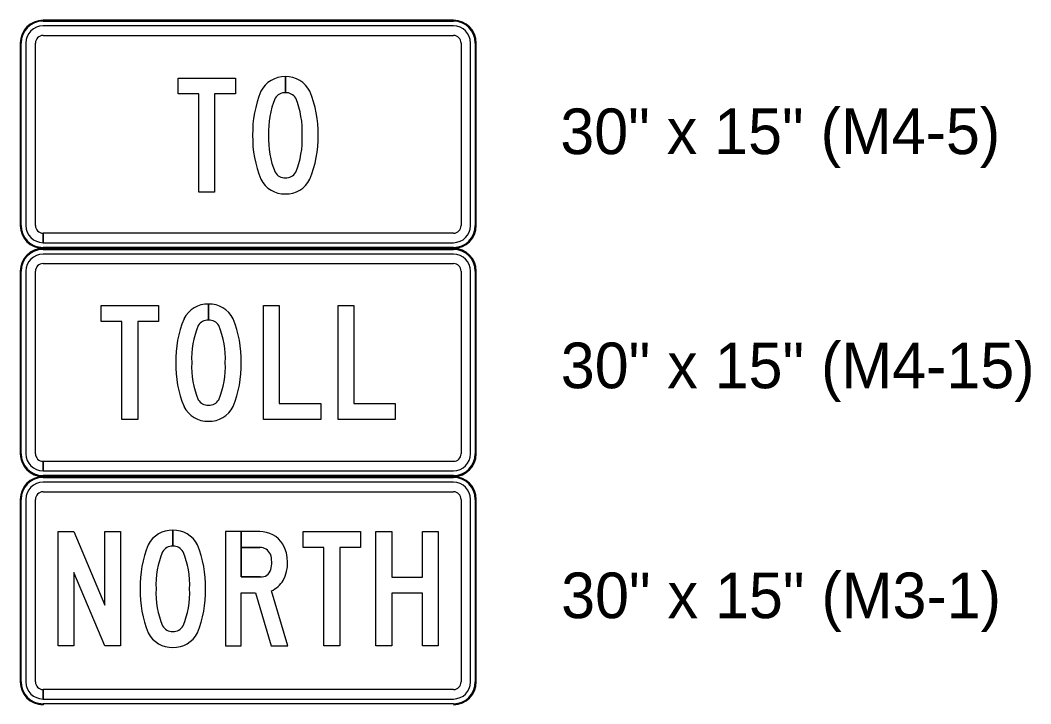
# Model space of a CAD drawing. Extents: x 17890587 to 17890754, y 17897693 to 17897992.
# Drawn here: x 17890612.323 to 17890616.81, y 17897879.973 to 17897883.006 of the extents above; entities that cross this region are included whole.
import ezdxf

# ---------------------------------------------------------------- set-up
doc = ezdxf.new("R2010")
doc.units = 0
for name, color, linetype in [('GSBWFill', 7, 'Continuous'), ('GSColorFill', 7, 'Continuous'), ('GSOutline', 7, 'Continuous'), ('TextMisc', 7, 'Continuous')]:
    doc.layers.add(name, color=color, linetype=linetype)

msp = doc.modelspace()

# ---------------------------------------------------------------- linework, layer by layer
at = {"layer": 'GSBWFill'}
for p, q in [((17890613.5003, 17897882.6844), (17890613.5003, 17897882.7557)), ((17890613.5003, 17897882.7557), (17890613.5003, 17897882.6844))]:
    msp.add_line(p, q, dxfattribs=at)
msp.add_lwpolyline([(17890613.1161, 17897882.6787), (17890613.0239, 17897882.6787), (17890613.0239, 17897882.7496), (17890613.2782, 17897882.7496), (17890613.2782, 17897882.6787), (17890613.1859, 17897882.6787), (17890613.1859, 17897882.2434), (17890613.1161, 17897882.2434)], close=True, dxfattribs=at)
for centre, major_axis, start_param, end_param in [((17890613.4962, 17897882.6365), (0, 0.1193), 6.248265, 7.383959), ((17890613.5044, 17897882.6365), (0, 0.1193), 5.182411, 6.317893), ((17890613.8275, 17897882.5051), (0, 0.48), 1.174158, 1.59042), ((17890613.173, 17897882.5051), (0, 0.48), 4.692766, 5.109028), ((17890613.7966, 17897882.5127), (0, 0.377), 1.169623, 1.616135), ((17890613.4976, 17897882.6335), (0, 0.051), 6.22959, 7.30809), ((17890613.503, 17897882.6335), (0, 0.051), 5.258281, 6.336283), ((17890613.204, 17897882.5127), (0, 0.377), 4.667051, 5.113562), ((17890613.8275, 17897882.4862), (0, 0.48), 1.551173, 1.967435), ((17890613.7966, 17897882.4786), (0, 0.377), 1.525458, 1.97197), ((17890613.204, 17897882.4786), (0, 0.377), 4.311216, 4.757727), ((17890613.173, 17897882.4862), (0, 0.48), 4.31575, 4.732012), ((17890613.4976, 17897882.3578), (0, 0.051), 2.116688, 3.195188), ((17890613.503, 17897882.3578), (0, 0.051), 3.087997, 4.166497), ((17890613.4962, 17897882.3548), (0, 0.1193), 2.040819, 3.176513), ((17890613.5044, 17897882.3548), (0, 0.1193), 3.106673, 4.242367)]:
    msp.add_ellipse(centre, major_axis=major_axis, ratio=0.985, start_param=start_param, end_param=end_param, dxfattribs=at)
at = {"layer": 'GSColorFill'}
for p, q in [((17890614.2465, 17897883.006), (17890612.4241, 17897883.006)), ((17890614.2465, 17897883.006), (17890612.4241, 17897883.006)), ((17890612.4241, 17897883.0018), (17890614.2465, 17897883.0018)), ((17890614.2465, 17897882.9807), (17890612.4241, 17897882.9807)), ((17890612.4241, 17897882.9385), (17890614.2465, 17897882.9385)), ((17890612.3229, 17897882.9048), (17890612.3229, 17897882.0949)), ((17890612.3229, 17897882.9048), (17890612.3229, 17897882.0949)), ((17890612.3271, 17897882.0949), (17890612.3271, 17897882.9048)), ((17890612.3482, 17897882.9048), (17890612.3482, 17897882.0949)), ((17890612.3904, 17897882.0949), (17890612.3904, 17897882.9048)), ((17890614.2802, 17897882.9048), (17890614.2802, 17897882.0949)), ((17890614.3224, 17897882.0949), (17890614.3224, 17897882.9048)), ((17890614.3435, 17897882.9048), (17890614.3435, 17897882.0949)), ((17890614.3477, 17897882.0949), (17890614.3477, 17897882.9048)), ((17890614.3477, 17897882.0949), (17890614.3477, 17897882.9048)), ((17890613.5003, 17897882.6844), (17890613.5003, 17897882.7557)), ((17890613.5003, 17897882.7557), (17890613.5003, 17897882.6844)), ((17890612.4241, 17897882.0189), (17890612.4241, 17897882.0611)), ((17890614.2465, 17897882.0611), (17890612.4246, 17897882.0611)), ((17890612.4246, 17897882.0611), (17890612.4246, 17897882.0189)), ((17890612.4246, 17897882.0189), (17890614.2465, 17897882.0189)), ((17890612.4241, 17897881.9936), (17890612.4241, 17897881.9979)), ((17890612.4241, 17897881.9936), (17890614.2465, 17897881.9936)), ((17890614.2465, 17897881.9979), (17890612.4242, 17897881.9979)), ((17890612.4242, 17897881.9979), (17890612.4242, 17897881.9936)), ((17890612.4242, 17897881.9936), (17890614.2465, 17897881.9936)), ((17890614.2465, 17897881.9936), (17890612.4242, 17897881.9936)), ((17890614.2465, 17897881.9936), (17890612.4242, 17897881.9936)), ((17890612.4242, 17897881.9894), (17890614.2465, 17897881.9894)), ((17890614.2465, 17897881.9683), (17890612.4242, 17897881.9683)), ((17890612.3229, 17897881.8924), (17890612.3229, 17897881.0825)), ((17890612.3229, 17897881.8924), (17890612.3229, 17897881.0825)), ((17890612.3271, 17897881.0825), (17890612.3271, 17897881.8924)), ((17890612.3482, 17897881.8924), (17890612.3482, 17897881.0825)), ((17890612.3904, 17897881.0825), (17890612.3904, 17897881.8924)), ((17890612.4242, 17897881.9261), (17890614.2465, 17897881.9261)), ((17890614.2802, 17897881.8924), (17890614.2802, 17897881.0825)), ((17890614.3224, 17897881.0825), (17890614.3224, 17897881.8924)), ((17890614.3435, 17897881.8924), (17890614.3435, 17897881.0825)), ((17890614.3477, 17897881.0825), (17890614.3477, 17897881.8924)), ((17890614.3477, 17897881.0825), (17890614.3477, 17897881.8924)), ((17890613.1589, 17897881.6754), (17890613.1589, 17897881.7467)), ((17890613.1589, 17897881.7467), (17890613.1589, 17897881.6754)), ((17890612.4242, 17897881.0065), (17890612.4242, 17897881.0487)), ((17890614.2465, 17897881.0487), (17890612.4246, 17897881.0487)), ((17890612.4246, 17897881.0487), (17890612.4246, 17897881.0065)), ((17890612.4242, 17897880.9812), (17890612.4242, 17897880.9855)), ((17890614.2465, 17897880.9855), (17890612.4242, 17897880.9855)), ((17890612.4242, 17897880.9855), (17890612.4242, 17897880.9812)), ((17890612.4246, 17897881.0065), (17890614.2465, 17897881.0065)), ((17890614.2465, 17897880.9812), (17890612.4242, 17897880.9812)), ((17890614.2465, 17897880.9812), (17890612.4242, 17897880.9812)), ((17890612.4242, 17897880.9812), (17890614.2465, 17897880.9812)), ((17890612.4242, 17897880.9812), (17890614.2465, 17897880.9812)), ((17890612.4242, 17897880.977), (17890614.2465, 17897880.977)), ((17890614.2465, 17897880.9559), (17890612.4242, 17897880.9559)), ((17890612.4242, 17897880.9137), (17890614.2465, 17897880.9137)), ((17890612.3229, 17897880.88), (17890612.3229, 17897880.0701)), ((17890612.3229, 17897880.88), (17890612.3229, 17897880.0701)), ((17890612.3272, 17897880.0701), (17890612.3272, 17897880.88)), ((17890612.3483, 17897880.88), (17890612.3483, 17897880.0701)), ((17890612.3904, 17897880.0701), (17890612.3904, 17897880.88)), ((17890614.2803, 17897880.88), (17890614.2803, 17897880.0701)), ((17890614.3224, 17897880.0701), (17890614.3224, 17897880.88)), ((17890614.3435, 17897880.88), (17890614.3435, 17897880.0701)), ((17890614.3477, 17897880.0701), (17890614.3477, 17897880.88)), ((17890614.3477, 17897880.0701), (17890614.3477, 17897880.88)), ((17890613.0005, 17897880.6718), (17890613.0005, 17897880.7431)), ((17890613.0005, 17897880.7431), (17890613.0005, 17897880.6718)), ((17890613.0005, 17897880.6718), (17890613.0005, 17897880.7431)), ((17890613.0005, 17897880.7431), (17890613.0005, 17897880.6718)), ((17890613.5106, 17897880.2307), (17890613.4384, 17897880.4736)), ((17890612.4242, 17897879.9941), (17890612.4242, 17897880.0363)), ((17890614.2465, 17897880.0363), (17890612.4246, 17897880.0363)), ((17890612.4246, 17897880.0363), (17890612.4246, 17897879.9941)), ((17890612.4242, 17897879.9688), (17890612.4242, 17897879.9731)), ((17890614.2465, 17897879.9731), (17890612.4242, 17897879.9731)), ((17890612.4242, 17897879.9731), (17890612.4242, 17897879.9688)), ((17890612.4246, 17897879.9941), (17890614.2465, 17897879.9941))]:
    msp.add_line(p, q, dxfattribs=at)
for points in [[(17890613.1161, 17897882.6787), (17890613.0239, 17897882.6787), (17890613.0239, 17897882.7496), (17890613.2782, 17897882.7496), (17890613.2782, 17897882.6787), (17890613.1859, 17897882.6787), (17890613.1859, 17897882.2434), (17890613.1161, 17897882.2434)], [(17890612.7747, 17897881.6697), (17890612.6825, 17897881.6697), (17890612.6825, 17897881.7405), (17890612.9368, 17897881.7405), (17890612.9368, 17897881.6697), (17890612.8445, 17897881.6697), (17890612.8445, 17897881.2343), (17890612.7747, 17897881.2343)], [(17890613.4027, 17897881.7405), (17890613.4725, 17897881.7405), (17890613.4725, 17897881.3052), (17890613.6569, 17897881.3052), (17890613.6569, 17897881.2343), (17890613.4027, 17897881.2343)], [(17890613.7339, 17897881.7405), (17890613.8037, 17897881.7405), (17890613.8037, 17897881.3052), (17890613.9881, 17897881.3052), (17890613.9881, 17897881.2343), (17890613.7339, 17897881.2343)], [(17890612.5612, 17897880.7369), (17890612.6986, 17897880.4109), (17890612.6986, 17897880.7369), (17890612.7684, 17897880.7369), (17890612.7684, 17897880.2307), (17890612.6986, 17897880.2307), (17890612.5615, 17897880.556), (17890612.5615, 17897880.2307), (17890612.4917, 17897880.2307), (17890612.4917, 17897880.7369)], [(17890612.5612, 17897880.7369), (17890612.6986, 17897880.4109), (17890612.6986, 17897880.7369), (17890612.7684, 17897880.7369), (17890612.7684, 17897880.2307), (17890612.6986, 17897880.2307), (17890612.5615, 17897880.556), (17890612.5615, 17897880.2307), (17890612.4917, 17897880.2307), (17890612.4917, 17897880.7369)], [(17890612.5612, 17897880.7369), (17890612.6986, 17897880.4109), (17890612.6986, 17897880.7369), (17890612.7684, 17897880.7369), (17890612.7684, 17897880.2307), (17890612.6986, 17897880.2307), (17890612.5615, 17897880.556), (17890612.5615, 17897880.2307), (17890612.4917, 17897880.2307), (17890612.4917, 17897880.7369)], [(17890613.6715, 17897880.666), (17890613.5793, 17897880.666), (17890613.5793, 17897880.7369), (17890613.8336, 17897880.7369), (17890613.8336, 17897880.666), (17890613.7413, 17897880.666), (17890613.7413, 17897880.2307), (17890613.6715, 17897880.2307)], [(17890613.6715, 17897880.666), (17890613.5793, 17897880.666), (17890613.5793, 17897880.7369), (17890613.8336, 17897880.7369), (17890613.8336, 17897880.666), (17890613.7413, 17897880.666), (17890613.7413, 17897880.2307), (17890613.6715, 17897880.2307)], [(17890613.6715, 17897880.666), (17890613.5793, 17897880.666), (17890613.5793, 17897880.7369), (17890613.8336, 17897880.7369), (17890613.8336, 17897880.666), (17890613.7413, 17897880.666), (17890613.7413, 17897880.2307), (17890613.6715, 17897880.2307)], [(17890613.9023, 17897880.7369), (17890613.9721, 17897880.7369), (17890613.9721, 17897880.5344), (17890614.1092, 17897880.5344), (17890614.1092, 17897880.7369), (17890614.179, 17897880.7369), (17890614.179, 17897880.2307), (17890614.1092, 17897880.2307), (17890614.1092, 17897880.4636), (17890613.9721, 17897880.4636), (17890613.9721, 17897880.2307), (17890613.9023, 17897880.2307)], [(17890613.9023, 17897880.7369), (17890613.9721, 17897880.7369), (17890613.9721, 17897880.5344), (17890614.1092, 17897880.5344), (17890614.1092, 17897880.7369), (17890614.179, 17897880.7369), (17890614.179, 17897880.2307), (17890614.1092, 17897880.2307), (17890614.1092, 17897880.4636), (17890613.9721, 17897880.4636), (17890613.9721, 17897880.2307), (17890613.9023, 17897880.2307)], [(17890613.9023, 17897880.7369), (17890613.9721, 17897880.7369), (17890613.9721, 17897880.5344), (17890614.1092, 17897880.5344), (17890614.1092, 17897880.7369), (17890614.179, 17897880.7369), (17890614.179, 17897880.2307), (17890614.1092, 17897880.2307), (17890614.1092, 17897880.4636), (17890613.9721, 17897880.4636), (17890613.9721, 17897880.2307), (17890613.9023, 17897880.2307)]]:
    msp.add_lwpolyline(points, close=True, dxfattribs=at)
for points in [[(17890613.3863, 17897880.7369), (17890613.2339, 17897880.7369), (17890613.2339, 17897880.2307), (17890613.3037, 17897880.2307), (17890613.3037, 17897880.4651), (17890613.3681, 17897880.4651), (17890613.4377, 17897880.2307), (17890613.5106, 17897880.2307)], [(17890613.3889, 17897880.536), (17890613.3037, 17897880.536), (17890613.3037, 17897880.7369), (17890613.2339, 17897880.7369), (17890613.2339, 17897880.2307)], [(17890613.3889, 17897880.536), (17890613.3037, 17897880.536), (17890613.3037, 17897880.7369), (17890613.2339, 17897880.7369), (17890613.2339, 17897880.2307)], [(17890613.3863, 17897880.7369), (17890613.3037, 17897880.7369), (17890613.3037, 17897880.666), (17890613.3863, 17897880.666)], [(17890613.3863, 17897880.7369), (17890613.3037, 17897880.7369), (17890613.3037, 17897880.666), (17890613.3863, 17897880.666)], [(17890613.3863, 17897880.666), (17890613.3037, 17897880.666), (17890613.3037, 17897880.536), (17890613.3889, 17897880.536)], [(17890613.2339, 17897880.2307), (17890613.3037, 17897880.2307), (17890613.3037, 17897880.4651), (17890613.3681, 17897880.4651), (17890613.4377, 17897880.2307), (17890613.5106, 17897880.2307), (17890613.4384, 17897880.4736)], [(17890613.2339, 17897880.2307), (17890613.3037, 17897880.2307), (17890613.3037, 17897880.4651), (17890613.3681, 17897880.4651), (17890613.4377, 17897880.2307), (17890613.5106, 17897880.2307), (17890613.4384, 17897880.4736)]]:
    msp.add_lwpolyline(points, dxfattribs=at)
for centre, radius, start, end in [((17890612.4241, 17897882.9048), 0.1012, 90, 180), ((17890612.4241, 17897882.9048), 0.1012, 90, 180), ((17890614.2465, 17897882.9048), 0.1012, 0, 90), ((17890614.2465, 17897882.9048), 0.1012, 0, 90), ((17890612.4241, 17897882.9048), 0.097, 90, 180), ((17890612.4241, 17897882.9048), 0.0759, 90, 180), ((17890614.2465, 17897882.9048), 0.097, 0, 90), ((17890614.2465, 17897882.9048), 0.0759, 0, 90), ((17890612.4241, 17897882.9048), 0.0337, 90, 180), ((17890614.2465, 17897882.9048), 0.0337, 0, 90), ((17890612.4241, 17897882.0949), 0.1012, 180, 270), ((17890612.4241, 17897882.0949), 0.1012, 180, 270), ((17890612.4241, 17897882.0949), 0.097, 180, 270), ((17890612.4241, 17897882.0949), 0.0759, 180, 270), ((17890612.4241, 17897882.0949), 0.0337, 180, 270), ((17890614.2465, 17897882.0949), 0.1012, 270, 0), ((17890614.2465, 17897882.0949), 0.1012, 270, 0), ((17890614.2465, 17897882.0949), 0.097, 270, 0), ((17890614.2465, 17897882.0949), 0.0759, 270, 0), ((17890614.2465, 17897882.0949), 0.0337, 270, 0), ((17890612.4242, 17897881.8924), 0.1012, 90, 180), ((17890612.4242, 17897881.8924), 0.1012, 90, 180), ((17890612.4242, 17897881.8924), 0.097, 90, 180), ((17890614.2465, 17897881.8924), 0.1012, 0, 90), ((17890614.2465, 17897881.8924), 0.1012, 0, 90), ((17890614.2465, 17897881.8924), 0.097, 0, 90), ((17890612.4242, 17897881.8924), 0.0759, 90, 180), ((17890614.2465, 17897881.8924), 0.0759, 0, 90), ((17890612.4242, 17897881.8924), 0.0337, 90, 180), ((17890614.2465, 17897881.8924), 0.0337, 0, 90), ((17890612.4242, 17897881.0825), 0.1012, 180, 270), ((17890612.4242, 17897881.0825), 0.1012, 180, 270), ((17890612.4242, 17897881.0825), 0.097, 180, 270), ((17890612.4242, 17897881.0825), 0.0759, 180, 270), ((17890612.4242, 17897881.0825), 0.0337, 180, 270), ((17890614.2465, 17897881.0825), 0.1012, 270, 0), ((17890614.2465, 17897881.0825), 0.0759, 270, 0), ((17890614.2465, 17897881.0825), 0.0337, 270, 0), ((17890614.2465, 17897881.0825), 0.1012, 270, 0), ((17890614.2465, 17897881.0825), 0.097, 270, 0), ((17890612.4242, 17897880.88), 0.1012, 90, 180), ((17890612.4242, 17897880.88), 0.1012, 90, 180), ((17890612.4242, 17897880.88), 0.097, 90, 180), ((17890612.4242, 17897880.88), 0.0759, 90, 180), ((17890614.2465, 17897880.88), 0.1012, 0, 90), ((17890614.2465, 17897880.88), 0.1012, 0, 90), ((17890614.2465, 17897880.88), 0.097, 0, 90), ((17890614.2465, 17897880.88), 0.0759, 0, 90), ((17890612.4242, 17897880.88), 0.0337, 90, 180), ((17890614.2465, 17897880.88), 0.0337, 0, 90), ((17890612.4242, 17897880.0701), 0.1012, 180, 270), ((17890612.4242, 17897880.0701), 0.1012, 180, 270), ((17890612.4242, 17897880.0701), 0.097, 180, 270), ((17890612.4242, 17897880.0701), 0.0759, 180, 270), ((17890612.4242, 17897880.0701), 0.0337, 180, 270), ((17890614.2465, 17897880.0701), 0.1012, 270, 0), ((17890614.2465, 17897880.0701), 0.1012, 270, 0), ((17890614.2465, 17897880.0701), 0.097, 270, 0), ((17890614.2465, 17897880.0701), 0.0759, 270, 0), ((17890614.2465, 17897880.0701), 0.0337, 270, 0)]:
    msp.add_arc(centre, radius, start, end, dxfattribs=at)
for centre, major_axis, ratio, start_param, end_param in [((17890613.4962, 17897882.6365), (0, 0.1193), 0.985, 6.248265, 7.383959), ((17890613.5044, 17897882.6365), (0, 0.1193), 0.985, 5.182411, 6.317893), ((17890613.8275, 17897882.5051), (0, 0.48), 0.985, 1.174158, 1.59042), ((17890613.173, 17897882.5051), (0, 0.48), 0.985, 4.692766, 5.109028), ((17890613.7966, 17897882.5127), (0, 0.377), 0.985, 1.169623, 1.616135), ((17890613.4976, 17897882.6335), (0, 0.051), 0.985, 6.22959, 7.30809), ((17890613.503, 17897882.6335), (0, 0.051), 0.985, 5.258281, 6.336283), ((17890613.204, 17897882.5127), (0, 0.377), 0.985, 4.667051, 5.113562), ((17890613.8275, 17897882.4862), (0, 0.48), 0.985, 1.551173, 1.967435), ((17890613.7966, 17897882.4786), (0, 0.377), 0.985, 1.525458, 1.97197), ((17890613.204, 17897882.4786), (0, 0.377), 0.985, 4.311216, 4.757727), ((17890613.173, 17897882.4862), (0, 0.48), 0.985, 4.31575, 4.732012), ((17890613.4976, 17897882.3578), (0, 0.051), 0.985, 2.116688, 3.195188), ((17890613.503, 17897882.3578), (0, 0.051), 0.985, 3.087997, 4.166497), ((17890613.4962, 17897882.3548), (0, 0.1193), 0.985, 2.040819, 3.176513), ((17890613.5044, 17897882.3548), (0, 0.1193), 0.985, 3.106673, 4.242367), ((17890613.1548, 17897881.6275), (0, 0.1193), 0.985, 6.248265, 7.383959), ((17890613.163, 17897881.6275), (0, 0.1193), 0.985, 5.182411, 6.317893), ((17890613.4862, 17897881.496), (0, 0.48), 0.985, 1.174158, 1.59042), ((17890613.1562, 17897881.6245), (0, 0.051), 0.985, 6.22959, 7.30809), ((17890613.1616, 17897881.6245), (0, 0.051), 0.985, 5.258281, 6.336283), ((17890612.8316, 17897881.496), (0, 0.48), 0.985, 4.692766, 5.109028), ((17890613.4552, 17897881.5037), (0, 0.377), 0.985, 1.169623, 1.616135), ((17890612.8626, 17897881.5037), (0, 0.377), 0.985, 4.667051, 5.113562), ((17890613.4862, 17897881.4772), (0, 0.48), 0.985, 1.551173, 1.967435), ((17890613.4552, 17897881.4695), (0, 0.377), 0.985, 1.525458, 1.97197), ((17890612.8626, 17897881.4695), (0, 0.377), 0.985, 4.311216, 4.757727), ((17890612.8316, 17897881.4772), (0, 0.48), 0.985, 4.31575, 4.732012), ((17890613.1562, 17897881.3488), (0, 0.051), 0.985, 2.116688, 3.195188), ((17890613.1616, 17897881.3488), (0, 0.051), 0.985, 3.087997, 4.166497), ((17890613.1548, 17897881.3458), (0, 0.1193), 0.985, 2.040819, 3.176513), ((17890613.163, 17897881.3458), (0, 0.1193), 0.985, 3.106673, 4.242367), ((17890612.9964, 17897880.6239), (0, 0.1193), 0.985082, 6.248265, 7.383959), ((17890612.9964, 17897880.6239), (0, 0.1193), 0.985082, 6.248265, 7.383959), ((17890612.9964, 17897880.6239), (0, 0.1193), 0.985082, 6.248265, 7.383959), ((17890613.0046, 17897880.6239), (0, 0.1193), 0.985082, 5.182411, 6.318105), ((17890613.0046, 17897880.6239), (0, 0.1193), 0.985082, 5.182411, 6.317893), ((17890613.0046, 17897880.6239), (0, 0.1193), 0.985082, 5.182411, 6.317893), ((17890613.3887, 17897880.6153), (0, 0.1217), 0.985082, 5.284461, 6.303565), ((17890613.3887, 17897880.6153), (0, 0.1217), 0.985082, 5.284461, 6.303565), ((17890613.3887, 17897880.6153), (0, 0.1217), 0.985082, 5.284461, 6.303565), ((17890613.3278, 17897880.4925), (0, 0.48), 0.985082, 1.174158, 1.59042), ((17890613.3278, 17897880.4925), (0, 0.48), 0.985082, 1.174158, 1.59042), ((17890613.3278, 17897880.4925), (0, 0.48), 0.985082, 1.174158, 1.59042), ((17890612.9978, 17897880.6209), (0, 0.051), 0.985082, 6.22959, 7.30809), ((17890612.9978, 17897880.6209), (0, 0.051), 0.985082, 6.22959, 7.30809), ((17890612.9978, 17897880.6209), (0, 0.051), 0.985082, 6.22959, 7.30809), ((17890613.0032, 17897880.6209), (0, 0.051), 0.985082, 5.258281, 6.33678), ((17890613.0032, 17897880.6209), (0, 0.051), 0.985082, 5.258281, 6.336283), ((17890613.0032, 17897880.6209), (0, 0.051), 0.985082, 5.258281, 6.336283), ((17890612.6732, 17897880.4925), (0, 0.48), 0.985082, 4.692766, 5.109028), ((17890612.6732, 17897880.4925), (0, 0.48), 0.985082, 4.692766, 5.109028), ((17890612.6732, 17897880.4925), (0, 0.48), 0.985082, 4.692766, 5.109028), ((17890613.3437, 17897880.5999), (0, 0.1689), 0.985082, 4.22428, 5.21411), ((17890613.3437, 17897880.5999), (0, 0.1689), 0.985082, 4.22428, 5.21411), ((17890613.3437, 17897880.5999), (0, 0.1689), 0.985082, 4.22428, 5.21411), ((17890613.2968, 17897880.5001), (0, 0.377), 0.985082, 1.169623, 1.616135), ((17890613.2968, 17897880.5001), (0, 0.377), 0.985082, 1.169623, 1.616135), ((17890613.2968, 17897880.5001), (0, 0.377), 0.985082, 1.169623, 1.616135), ((17890612.7042, 17897880.5001), (0, 0.377), 0.985082, 4.667051, 5.113562), ((17890612.7042, 17897880.5001), (0, 0.377), 0.985082, 4.667051, 5.113562), ((17890612.7042, 17897880.5001), (0, 0.377), 0.985082, 4.667051, 5.113562), ((17890613.3881, 17897880.614), (0, 0.0521), 0.985082, 5.168949, 6.317293), ((17890613.3881, 17897880.614), (0, 0.0521), 0.985082, 5.168949, 6.317293), ((17890613.3881, 17897880.614), (0, 0.0521), 0.985082, 5.168949, 6.317293), ((17890613.3108, 17897880.5996), (0, 0.1307), 0.985082, 4.469957, 5.002454), ((17890613.3108, 17897880.5996), (0, 0.1307), 0.985082, 4.469957, 5.002454), ((17890613.3108, 17897880.5996), (0, 0.1307), 0.985082, 4.469957, 5.002454), ((17890613.3927, 17897880.5815), (0, 0.0457), 0.985082, 3.056737, 4.417555), ((17890613.3927, 17897880.5815), (0, 0.0457), 0.985082, 3.056737, 4.417555), ((17890613.3927, 17897880.5815), (0, 0.0457), 0.985082, 3.056737, 4.417555), ((17890613.3893, 17897880.5831), (0, 0.1203), 0.985082, 3.569693, 4.167803), ((17890613.3893, 17897880.5831), (0, 0.1203), 0.985082, 3.569693, 4.167803), ((17890613.3893, 17897880.5831), (0, 0.1203), 0.985082, 3.569693, 4.167803), ((17890613.3278, 17897880.4736), (0, 0.48), 0.985082, 1.551173, 1.967435), ((17890613.3278, 17897880.4736), (0, 0.48), 0.985082, 1.551173, 1.967435), ((17890613.3278, 17897880.4736), (0, 0.48), 0.985082, 1.551173, 1.967435), ((17890613.2968, 17897880.466), (0, 0.377), 0.985082, 1.525458, 1.97197), ((17890613.2968, 17897880.466), (0, 0.377), 0.985082, 1.525458, 1.97197), ((17890613.2968, 17897880.466), (0, 0.377), 0.985082, 1.525458, 1.97197), ((17890612.7042, 17897880.466), (0, 0.377), 0.985082, 4.311216, 4.757727), ((17890612.7042, 17897880.466), (0, 0.377), 0.985082, 4.311216, 4.757727), ((17890612.7042, 17897880.466), (0, 0.377), 0.985082, 4.311216, 4.757727), ((17890612.6732, 17897880.4736), (0, 0.48), 0.985082, 4.31575, 4.732012), ((17890612.6732, 17897880.4736), (0, 0.48), 0.985082, 4.31575, 4.732012), ((17890612.6732, 17897880.4736), (0, 0.48), 0.985082, 4.31575, 4.732012), ((17890612.9978, 17897880.3452), (0, 0.051), 0.985082, 2.116688, 3.195188), ((17890612.9978, 17897880.3452), (0, 0.051), 0.985082, 2.116688, 3.195188), ((17890612.9978, 17897880.3452), (0, 0.051), 0.985082, 2.116688, 3.195188), ((17890613.0032, 17897880.3452), (0, 0.051), 0.985082, 3.087997, 4.166497), ((17890613.0032, 17897880.3452), (0, 0.051), 0.985082, 3.087997, 4.166497), ((17890613.0032, 17897880.3452), (0, 0.051), 0.985082, 3.087997, 4.166497), ((17890612.9964, 17897880.3422), (0, 0.1193), 0.985082, 2.040819, 3.176513), ((17890612.9964, 17897880.3422), (0, 0.1193), 0.985082, 2.040819, 3.176513), ((17890612.9964, 17897880.3422), (0, 0.1193), 0.985082, 2.040819, 3.176513), ((17890613.0046, 17897880.3422), (0, 0.1193), 0.985082, 3.106673, 4.242367), ((17890613.0046, 17897880.3422), (0, 0.1193), 0.985082, 3.106673, 4.242367), ((17890613.0046, 17897880.3422), (0, 0.1193), 0.985082, 3.106673, 4.242367)]:
    msp.add_ellipse(centre, major_axis=major_axis, ratio=ratio, start_param=start_param, end_param=end_param, dxfattribs=at)
at = {"layer": 'GSOutline'}
msp.add_lwpolyline([(17890613.1161, 17897882.6787), (17890613.0239, 17897882.6787), (17890613.0239, 17897882.7496), (17890613.2782, 17897882.7496), (17890613.2782, 17897882.6787), (17890613.1859, 17897882.6787), (17890613.1859, 17897882.2434), (17890613.1161, 17897882.2434)], close=True, dxfattribs=at)
for centre, major_axis, start_param, end_param in [((17890613.4962, 17897882.6365), (0, 0.1193), 6.248265, 7.383959), ((17890613.5044, 17897882.6365), (0, 0.1193), 5.182411, 6.318105), ((17890613.8275, 17897882.5051), (0, 0.48), 1.174158, 1.59042), ((17890613.173, 17897882.5051), (0, 0.48), 4.692766, 5.109028), ((17890613.7966, 17897882.5127), (0, 0.377), 1.169623, 1.616135), ((17890613.4976, 17897882.6335), (0, 0.051), 6.22959, 7.30809), ((17890613.503, 17897882.6335), (0, 0.051), 5.258281, 6.33678), ((17890613.204, 17897882.5127), (0, 0.377), 4.667051, 5.113562), ((17890613.8275, 17897882.4862), (0, 0.48), 1.551173, 1.967435), ((17890613.7966, 17897882.4786), (0, 0.377), 1.525458, 1.97197), ((17890613.204, 17897882.4786), (0, 0.377), 4.311216, 4.757727), ((17890613.173, 17897882.4862), (0, 0.48), 4.31575, 4.732012), ((17890613.4976, 17897882.3578), (0, 0.051), 2.116688, 3.195188), ((17890613.503, 17897882.3578), (0, 0.051), 3.087997, 4.166497), ((17890613.4962, 17897882.3548), (0, 0.1193), 2.040819, 3.176513), ((17890613.5044, 17897882.3548), (0, 0.1193), 3.106673, 4.242367)]:
    msp.add_ellipse(centre, major_axis=major_axis, ratio=0.985, start_param=start_param, end_param=end_param, dxfattribs=at)

# ---------------------------------------------------------------- texts
at = {"layer": 'TextMisc'}
for s, p in [('30" x 15" (M4-5)', (17890614.7208, 17897882.4119)), ('30" x 15" (M4-15)', (17890614.7229, 17897881.3732)), ('30" x 15" (M3-1)', (17890614.7245, 17897880.3529))]:
    msp.add_text(s, height=0.202479, dxfattribs=at).set_placement(p)

doc.saveas('drawing.dxf')
